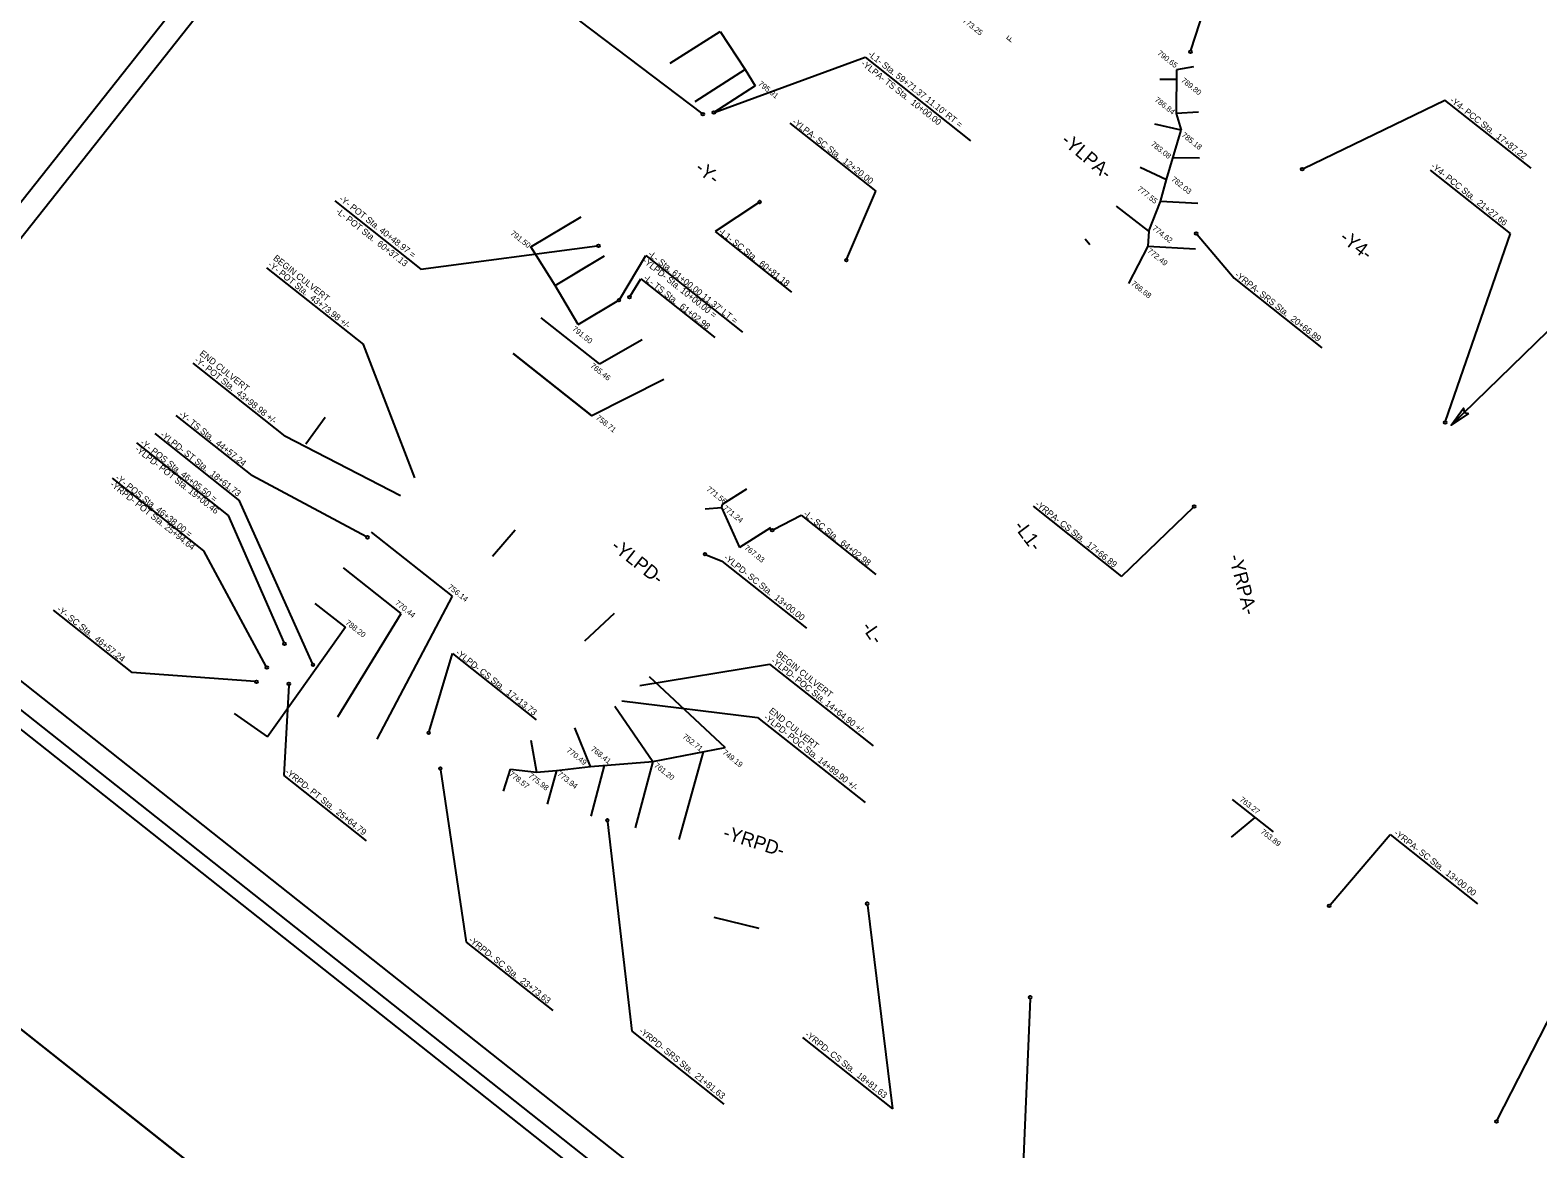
# Model space of a CAD drawing. Extents: x 1780292 to 1784627, y 810983 to 814799.
# Drawn here: x 1781173 to 1782828, y 812380 to 813608 of the extents above; entities that cross this region are included whole.
import ezdxf

# ---------------------------------------------------------------- set-up
doc = ezdxf.new("R2010")
doc.units = 0
for name, color, linetype in [('Exist XS Ground Line', 7, 'Continuous'), ('Prop Horizontal Alignment Station Label', 7, 'Continuous'), ('Prop Shear Point Element on Plans', 7, 'Continuous'), ('Prop Shear Point Label', 7, 'Continuous'), ('Prop SS Fill Line', 7, 'Continuous'), ('Prop Terminator CELL', 7, 'Continuous'), ('Sheet Clip Boundary CELL', 7, 'Continuous'), ('Sheet Cutting Line CELL', 7, 'Continuous'), ('Sheet Detail CELL', 7, 'Continuous'), ('Sheet Plot Border Inside CELL', 7, 'Continuous'), ('Sheet Plot Border Outside CELL', 7, 'Continuous')]:
    doc.layers.add(name, color=color, linetype=linetype)

msp = doc.modelspace()

# ---------------------------------------------------------------- linework, layer by layer
at = {"layer": 'Prop Horizontal Alignment Station Label'}
for p, q in [((1782447.4, 813585.4), (1782489.7, 813718.3)), ((1781776.1, 813618), (1781910.2, 813516.6)), ((1781924.9, 813517.8), (1782089.6, 813578.2)), ((1782089.6, 813578.2), (1782205.4, 813486.5)), ((1782570.8, 813455.8), (1782726.2, 813531.1)), ((1782820.7, 813456.3), (1782726.2, 813531.1)), ((1782007.1, 813505.6), (1782101.4, 813430.9)), ((1782798.2, 813384.5), (1782710.4, 813454)), ((1782069.7, 813356.7), (1782101.4, 813430.9)), ((1781507.5, 813420.5), (1781602.1, 813345.6)), ((1781972.7, 813418.4), (1781925.1, 813386.8)), ((1782733.1, 813174.3), (1782985, 813419.7)), ((1781602.1, 813345.6), (1781795.5, 813371)), ((1781925.1, 813386.8), (1782008.9, 813320.4)), ((1782454.2, 813383.5), (1782494.7, 813335.6)), ((1782726.8, 813178.8), (1782798.2, 813384.5)), ((1781820.3, 813312.7), (1781848.9, 813360.5)), ((1781848.9, 813360.5), (1781955.2, 813276.4)), ((1781432.5, 813347), (1781539, 813262.6)), ((1781831.7, 813316), (1781843.5, 813334.8)), ((1781843.5, 813334.8), (1781924.8, 813270.5)), ((1782494.7, 813335.6), (1782591.1, 813259.2)), ((1781595.3, 813116.5), (1781539, 813262.6)), ((1781351.7, 813242.3), (1781452.7, 813162.3)), ((1781333.1, 813185), (1781416.3, 813119.1)), ((1781310, 813165), (1781403, 813091.3)), ((1781579.6, 813096.7), (1781452.7, 813162.3)), ((1781390.8, 813075.2), (1781290.3, 813154.7)), ((1781363.9, 813036.4), (1781263.4, 813115.9)), ((1781542.2, 813051.8), (1781416.3, 813119.1)), ((1781482.9, 812912.5), (1781403, 813091.3)), ((1781451.8, 812935.5), (1781390.8, 813075.2)), ((1781989, 813059.7), (1782019.5, 813075.3)), ((1782019.5, 813075.3), (1782101.5, 813010.4)), ((1782274, 813085.2), (1782371.3, 813008.2)), ((1782449.9, 813084), (1782371.3, 813008.2)), ((1781432.3, 812909.4), (1781363.9, 813036.4)), ((1781915.3, 813031.9), (1781932.6, 813025.1)), ((1782025.7, 812951.4), (1781932.6, 813025.1)), ((1781198.5, 812971), (1781284.9, 812902.6)), ((1781611.1, 812838), (1781636.9, 812923.5)), ((1781636.9, 812923.5), (1781728.6, 812850.9)), ((1781842.5, 812888.3), (1781984.8, 812912)), ((1781984.8, 812912), (1782098.4, 812822.1)), ((1781420.2, 812892.7), (1781284.9, 812902.6)), ((1781456.9, 812888.9), (1781451.4, 812789.6)), ((1781822.7, 812871.6), (1781971.7, 812853.3)), ((1781971.7, 812853.3), (1782089.6, 812760)), ((1781623.6, 812795.8), (1781651.7, 812606.9)), ((1781451.4, 812789.6), (1781541.8, 812718.1)), ((1781806.8, 812739), (1781833.6, 812508.9)), ((1782600.1, 812647.8), (1782665.9, 812724.8)), ((1782665.9, 812724.8), (1782761.9, 812648.8)), ((1782092.2, 812647.5), (1782119.6, 812423.8)), ((1781651.7, 812606.9), (1781746.7, 812531.6)), ((1782270.7, 812544.7), (1782262.6, 812345.3)), ((1782783.5, 812411.2), (1782845.8, 812532.8)), ((1781833.6, 812508.9), (1781934.6, 812429)), ((1782020.8, 812502), (1782119.6, 812423.8))]:
    msp.add_line(p, q, dxfattribs=at)
for centre in [(1782446.9, 813584), (1781911.4, 813515.7), (1781923.5, 813517.3), (1782569.5, 813455.2), (1781973.9, 813419.2), (1781797, 813371.2), (1782453.2, 813384.7), (1782069.1, 813355.3), (1781819.5, 813311.4), (1781830.9, 813314.8), (1782726.5, 813177.3), (1782451, 813085), (1781987.6, 813059), (1781543.5, 813051.1), (1781913.9, 813032.5), (1781452.4, 812934.2), (1781433, 812908.1), (1781483.6, 812911.1), (1781421.7, 812892.6), (1781457, 812890.4), (1781610.6, 812836.5), (1781623.4, 812797.3), (1781806.7, 812740.5), (1782092, 812649), (1782599.1, 812646.7), (1782270.8, 812546.2), (1782782.8, 812409.9)]:
    msp.add_circle(centre, 1.5, dxfattribs=at)
at = {"layer": 'Prop Shear Point Element on Plans'}
for p, q in [((1781875.8, 813571.5), (1781930.7, 813606.3)), ((1781930.7, 813606.3), (1781958, 813564.7)), ((1781958, 813564.7), (1781902.7, 813529.3)), ((1781958, 813564.7), (1781969, 813546.6)), ((1782413.3, 813554.2), (1782431.4, 813554.1)), ((1782431.4, 813564.2), (1782431.2, 813516.2)), ((1782450.1, 813567.4), (1782431.4, 813564.2)), ((1781969, 813546.6), (1781923.5, 813517.3)), ((1782436.6, 813498.1), (1782407.7, 813504.6)), ((1782455.6, 813517.7), (1782431.2, 813516.2)), ((1782431.2, 813516.2), (1782436.6, 813498.1)), ((1782420.4, 813443.8), (1782436.6, 813498.1)), ((1782391.5, 813457.3), (1782420.4, 813443.8)), ((1782427.7, 813468), (1782456.7, 813467.7)), ((1782413.9, 813419.8), (1782420.4, 813443.8)), ((1782401.2, 813387.3), (1782365.6, 813414.7)), ((1782401.2, 813387.3), (1782413.9, 813419.8)), ((1782455, 813417.7), (1782413.9, 813419.8)), ((1781722.7, 813369.9), (1781777.8, 813403)), ((1782331.1, 813378.7), (1782336.2, 813372.6)), ((1782401.2, 813387.3), (1782399.9, 813370.8)), ((1781749.4, 813327.6), (1781722.7, 813369.9)), ((1781749.4, 813327.6), (1781803.6, 813360.2)), ((1781771.7, 813341), (1781803.6, 813360.2)), ((1782399.9, 813370.8), (1782378.8, 813329.8)), ((1782399.9, 813370.8), (1782452.2, 813367.8)), ((1781774.8, 813284.6), (1781749.4, 813327.6)), ((1781774.8, 813284.6), (1781819.5, 813311.4)), ((1781798.2, 813241.4), (1781734.2, 813292)), ((1781798.2, 813241.4), (1781845, 813268.4)), ((1781789.7, 813184.3), (1781703.2, 813252.8)), ((1781703.2, 813252.8), (1781789.7, 813184.3)), ((1781868.9, 813224.5), (1781789.7, 813184.3)), ((1781959.3, 813103.8), (1781932.7, 813087.1)), ((1781914.1, 813082.4), (1781932, 813084)), ((1781932.7, 813087.1), (1781932, 813084)), ((1781932, 813084), (1781951.9, 813039.8)), ((1781636.9, 812986.4), (1781548, 813056.8)), ((1781986, 813061.5), (1781951.9, 813039.8)), ((1781580.4, 812967.6), (1781517, 813017.6)), ((1781519.2, 812952.5), (1781486, 812978.4)), ((1781554.1, 812829.4), (1781636.9, 812986.4)), ((1781510.7, 812854.1), (1781580.4, 812967.6)), ((1781519.2, 812952.5), (1781469, 812881.7)), ((1781852.6, 812898.4), (1781936, 812820.4)), ((1781469, 812881.7), (1781433.8, 812832)), ((1781814.8, 812865.9), (1781856.6, 812805.2)), ((1781396.9, 812857.7), (1781433.8, 812832)), ((1781788.3, 812799.4), (1781770.9, 812842.1)), ((1781722.9, 812828.3), (1781729, 812793.3)), ((1781856.6, 812805.2), (1781936, 812820.4)), ((1781885.5, 812719.4), (1781912.2, 812815.8)), ((1781692.7, 812772.5), (1781700.4, 812796.7)), ((1781700.4, 812796.7), (1781729, 812793.3)), ((1781729, 812793.3), (1781750.9, 812795.1)), ((1781751, 812795.1), (1781740.7, 812758.3)), ((1781750.9, 812795.1), (1781788.3, 812799.4)), ((1781788.3, 812799.4), (1781856.6, 812805.2)), ((1781788.9, 812745.2), (1781803.6, 812800.7)), ((1781856.6, 812805.2), (1781837.2, 812732.4)), ((1782492.5, 812763.3), (1782537.7, 812727.7)), ((1782517.5, 812743.6), (1782491.7, 812722.1))]:
    msp.add_line(p, q, dxfattribs=at)
at = {"layer": 'Prop SS Fill Line'}
for p, q in [((1781496.8, 813182.5), (1781475.7, 813153.4)), ((1781705.5, 813058.8), (1781680.7, 813030.1)), ((1781782, 812937.4), (1781814.7, 812967.9)), ((1781923.5, 812634.1), (1781972.9, 812622))]:
    msp.add_line(p, q, dxfattribs=at)
at = {"layer": 'Prop Terminator CELL'}
msp.add_lwpolyline([(1782751.9, 813187.2), (1782733.1, 813174.3), (1782746.5, 813192.9), (1782747.3, 813188.1)], close=True, dxfattribs=at)
at = {"layer": 'Sheet Clip Boundary CELL'}
msp.add_lwpolyline([(1781927.1, 814345.3), (1784094.1, 812630.7), (1783998.7, 812510.2), (1784155.1, 812386.4), (1783319, 811330.3), (1782987.6, 811592.6), (1782917.5, 811504.1), (1780926, 813080.8)], close=True, dxfattribs=at)
at = {"layer": 'Sheet Cutting Line CELL'}
msp.add_line((1780451.8, 813073.9), (1783092.4, 810983.3), dxfattribs=at)
at = {"layer": 'Sheet Detail CELL'}
msp.add_lwpolyline([(1781915.6, 814370.3), (1784267.7, 812508.1), (1783243.5, 811214.5), (1780891.4, 813076.6)], close=True, dxfattribs=at)
at = {"layer": 'Sheet Plot Border Inside CELL'}
msp.add_lwpolyline([(1784297.9, 812505.9), (1781710.6, 814554.3), (1780665.3, 813234), (1783252.6, 811185.6)], close=True, dxfattribs=at)
at = {"layer": 'Sheet Plot Border Outside CELL'}
msp.add_lwpolyline([(1784458, 812708.2), (1781817.4, 814798.8), (1780451.8, 813073.9), (1783092.4, 810983.3)], close=True, dxfattribs=at)

# ---------------------------------------------------------------- texts
at = {"layer": 'Exist XS Ground Line'}
msp.add_text('F', height=7, rotation=51.6309, dxfattribs=at).set_placement((1782249.5, 813593.6))
at = {"layer": 'Prop Horizontal Alignment Station Label'}
for s, height, rotation, p in [('-YLPA- TS Sta.  10+00.00', 7, 321.7606, (1782084.7, 813570)), ("-L1- Sta. 59+71.37 11.10' RT =", 7, 321.6309, (1782092.3, 813580.2)), ('-Y4- PCC Sta.  17+87.22', 7, 321.9044, (1782731, 813529.6)), ('-YLPA- SC Sta.  12+20.00', 7, 321.8359, (1782009.2, 813506)), ('-YLPA-', 15, 319.7224, (1782303.7, 813484.9)), ('-Y-', 15, 321.1287, (1781901.9, 813454.2)), ('-Y4- PCC Sta.  21+27.66', 7, 321.3094, (1782710.2, 813457.4)), ('-Y- POT Sta. 40+48.97 =', 7, 321.6309, (1781511.7, 813421.5)), ('-L- POT Sta.  60+37.13', 7, 321.7606, (1781508, 813407.8)), ('-L1- SC Sta.  60+81.18', 7, 321.6014, (1781928.2, 813385.5)), ('-Y4-', 15, 322.4062, (1782609.5, 813377.8)), ('BEGIN CULVERT ', 7, 321.6309, (1781439.3, 813356.3)), ('-YLPD- Sta. 10+00.00 =', 7, 321.6309, (1781844.9, 813353.3)), ("-L- Sta. 61+00.00 11.37' LT =", 7, 321.6309, (1781850.8, 813360.8)), ('-Y- POT Sta.  43+73.98 +/-', 7, 321.6309, (1781433.6, 813349.2)), ('-YRPA- SRS Sta.  20+66.89', 7, 321.6398, (1782494.9, 813338.1)), ('-L- TS Sta.  61+02.98', 7, 321.5833, (1781845.9, 813334.6)), ('END CULVERT ', 7, 321.6309, (1781358.5, 813251.7)), ('-Y- POT Sta.  43+98.98 +/-', 7, 321.6309, (1781352.8, 813244.5)), ('-Y- TS Sta.  44+57.24', 7, 321.6309, (1781335.7, 813185)), ('-Y- POS Sta. 46+05.50 =', 7, 321.6309, (1781293.3, 813154)), ('-YLPD- ST Sta.  18+61.73', 7, 321.825, (1781315.3, 813162.7)), ('-YLPD- POT Sta. 19+00.46', 7, 321.6309, (1781287.6, 813146.8)), ('-YRPD- POT Sta. 25+94.64', 7, 321.6309, (1781260.3, 813108.1)), ('-Y- POS Sta. 46+38.00 =', 7, 321.6309, (1781266, 813115.3)), ('-YRPA- CS Sta.  17+66.89', 7, 321.5724, (1782275.8, 813086.4)), ('-L- SC Sta.  64+02.98', 7, 321.5965, (1782021.4, 813075.6)), ('-L1-', 15, 306.7891, (1782252.1, 813063.1)), ('-YLPD-', 15, 321.7204, (1781809.7, 813039)), ('-YLPD- SC Sta.  13+00.00', 7, 321.4231, (1781934, 813027.7)), ('-YRPA-', 15, 284.7056, (1782488.7, 813030.4)), ('-Y- SC Sta.  46+57.24', 7, 321.4816, (1781201.9, 812970.9)), ('-L-', 15, 304.7223, (1782085.1, 812952.5)), ('-YLPD- CS Sta.  17+13.73', 7, 321.6624, (1781639.6, 812923.3)), ('BEGIN CULVERT ', 7, 321.6309, (1781991.6, 812921.4)), ('-YLPD- POC Sta. 14+64.90 +/-', 7, 321.6309, (1781985.9, 812914.2)), ('END CULVERT ', 7, 321.6309, (1781983.5, 812859.3)), ('-YLPD- POC Sta. 14+89.90 +/-', 7, 321.6309, (1781977.8, 812852.2)), ('-YRPD- PT Sta.  25+64.79', 7, 321.4728, (1781452.4, 812792.4)), ('-YRPD-', 15, 342.4039, (1781932.7, 812720.9)), ('-YRPA- SC Sta.  13+00.00', 7, 321.9589, (1782669.7, 812725.3)), ('-YRPD- SC Sta.  23+73.63', 7, 321.5689, (1781653.7, 812608)), ('-YRPD- SRS Sta.  21+81.63', 7, 321.0861, (1781840.9, 812508)), ('-YRPD- CS Sta.  18+81.63', 7, 321.5678, (1782023.1, 812504.2))]:
    msp.add_text(s, height=height, rotation=rotation, dxfattribs=at).set_placement(p)
at = {"layer": 'Prop Shear Point Element on Plans'}
for s, p in [('790.65', (1782410, 813581.6)), ('789.80', (1782436.1, 813551.7)), ('795.91', (1781971.8, 813548)), ('786.84', (1782407, 813530.4)), ('785.18', (1782436.6, 813491.7)), ('791.50', (1781699.8, 813383.9)), ('791.50', (1781767.6, 813278.9)), ('765.46', (1781787.5, 813238.4)), ('758.71', (1781793.6, 813181.4)), ('771.56', (1781915, 813103)), ('771.24', (1781933, 813082.2)), ('767.83', (1781956.5, 813038.6)), ('756.14', (1781631, 812995.5)), ('770.44', (1781573.1, 812978)), ('788.20', (1781518.7, 812956.4)), ('752.71', (1781888.7, 812831.4)), ('778.57', (1781698.2, 812790.3)), ('775.98', (1781719.6, 812788.4)), ('763.27', (1782500.2, 812762.2)), ('763.89', (1782523.3, 812727))]:
    msp.add_text(s, height=6, rotation=321.6309, dxfattribs=at).set_placement(p)
at = {"layer": 'Prop Shear Point Label'}
for s, p in [('773.25', (1782196.1, 813617.3)), ('783.08', (1782402.8, 813481.8)), ('782.03', (1782425.2, 813443.1)), ('777.55', (1782387.9, 813432.5)), ('774.62', (1782404.4, 813389.4)), ('772.49', (1782399, 813364.4)), ('766.68', (1782381.1, 813328.7)), ('770.49', (1781761.3, 812816.3)), ('768.41', (1781788, 812817.7)), ('749.19', (1781932.6, 812813.9)), ('773.94', (1781751.3, 812790.3)), ('761.20', (1781857.6, 812799.7))]:
    msp.add_text(s, height=6, rotation=321.6309, dxfattribs=at).set_placement(p)
at = {"layer": 'Sheet Detail CELL'}
for s, rotation, p in [('TO PLOT FULL SIZE 62"X34"', 51.6309, (1780692, 813521.9)), ('TO PLOT 34"(HALF SIZE)', 321.6309, (1780513.5, 812643.3))]:
    msp.add_text(s, height=75, rotation=rotation, dxfattribs=at).set_placement(p)

doc.saveas('drawing.dxf')
